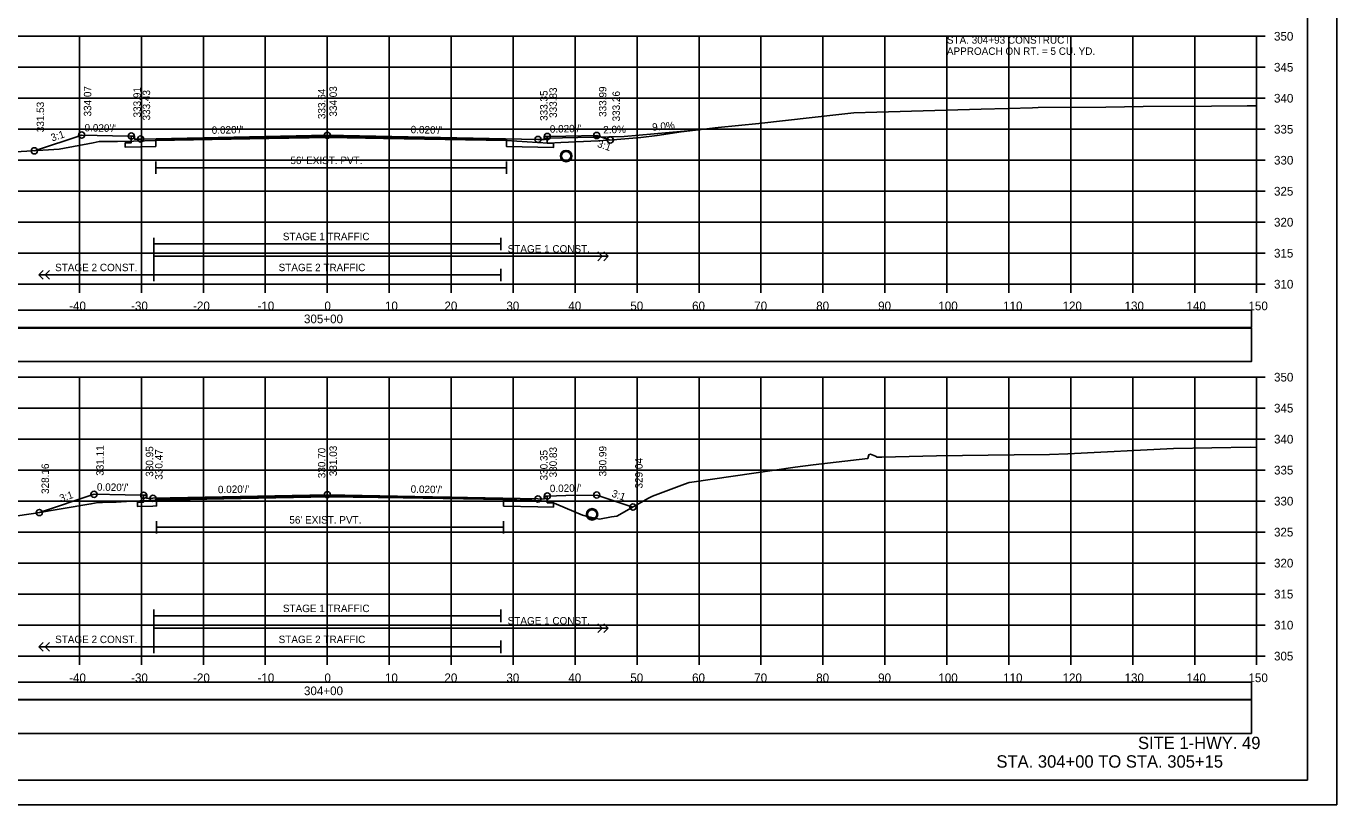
# Model space of a CAD drawing. Extents: x 1368122 to 1710785, y 373130 to 557566.
# Drawn here: x 1369307 to 1369518.5, y 373343.7 to 373469.3 of the extents above; entities that cross this region are included whole.
import ezdxf

# ---------------------------------------------------------------- set-up
doc = ezdxf.new("R2010")
doc.units = 0
for name, color, linetype in [('R_Alt Surface', 7, 'Continuous'), ('R_Axis', 7, 'Continuous'), ('R_Axis Annot', 7, 'Continuous'), ('R_Border', 7, 'Continuous'), ('R_Draft', 7, 'Continuous'), ('R_Drive', 7, 'Continuous'), ('R_Exist Surface', 7, 'Continuous'), ('R_Fin Surface', 7, 'Continuous'), ('R_Grid', 7, 'Continuous'), ('R_No Plot', 7, 'Continuous'), ('R_Striping', 7, 'Continuous'), ('R_Water', 7, 'Continuous'), ('R_Water Annot', 7, 'Continuous'), ('R_Xsect Elev', 7, 'Continuous'), ('R_Xsect Slope', 7, 'Continuous')]:
    doc.layers.add(name, color=color, linetype=linetype)

msp = doc.modelspace()

# ---------------------------------------------------------------- linework, layer by layer
for points in [[(1369206.41, 373420.64), (1369504.71, 373420.64), (1369504.71, 373423.46), (1369206.41, 373423.46)], [(1369206.41, 373415.17), (1369504.71, 373415.17), (1369504.71, 373420.58), (1369206.41, 373420.58)], [(1369206.41, 373360.64), (1369504.71, 373360.64), (1369504.71, 373363.46), (1369206.41, 373363.46)], [(1369206.41, 373355.17), (1369504.71, 373355.17), (1369504.71, 373360.58), (1369206.41, 373360.58)]]:
    msp.add_lwpolyline(points, close=True)
at = {"layer": 'R_Alt Surface'}
for points in [[(1369391.06, 373451.48), (1369391.06, 373450.39), (1369392.06, 373450.37), (1369392.06, 373449.7), (1369389.56, 373449.75), (1369384.51, 373449.85), (1369384.51, 373450.93), (1369355.56, 373451.51), (1369327.87, 373450.95), (1369327.87, 373449.87), (1369325.42, 373449.82), (1369322.92, 373449.77), (1369322.92, 373450.44), (1369323.92, 373450.46), (1369323.92, 373451.55)], [(1369327.87, 373447.43), (1369327.87, 373445.43)], [(1369327.87, 373446.43), (1369384.51, 373446.43)], [(1369384.51, 373447.43), (1369384.51, 373445.43)], [(1369391.06, 373393.48), (1369391.06, 373392.39), (1369392.06, 373392.37), (1369392.06, 373391.7), (1369389.56, 373391.75), (1369384.02, 373391.86), (1369384.02, 373392.94), (1369355.56, 373393.51), (1369328.01, 373392.96), (1369328.01, 373391.88), (1369327.42, 373391.86), (1369324.92, 373391.81), (1369324.92, 373392.48), (1369325.92, 373392.5), (1369325.92, 373393.59)], [(1369328.01, 373389.43), (1369328.01, 373387.43)], [(1369384.02, 373389.43), (1369384.02, 373387.43)], [(1369328.01, 373388.43), (1369384.02, 373388.43)]]:
    msp.add_lwpolyline(points, dxfattribs=at)
at = {"layer": 'R_Axis'}
for p, q in [((1369505.56, 373427.65), (1369505.56, 373467.65)), ((1369506.96, 373467.65), (1369505.56, 373467.65)), ((1369506.96, 373462.65), (1369505.56, 373462.65)), ((1369506.96, 373457.65), (1369505.56, 373457.65)), ((1369506.96, 373452.65), (1369505.56, 373452.65)), ((1369506.96, 373447.65), (1369505.56, 373447.65)), ((1369506.96, 373442.65), (1369505.56, 373442.65)), ((1369506.96, 373437.65), (1369505.56, 373437.65)), ((1369506.96, 373432.65), (1369505.56, 373432.65)), ((1369205.56, 373427.65), (1369505.56, 373427.65)), ((1369315.56, 373426.25), (1369315.56, 373427.65)), ((1369325.56, 373426.25), (1369325.56, 373427.65)), ((1369335.56, 373426.25), (1369335.56, 373427.65)), ((1369345.56, 373426.25), (1369345.56, 373427.65)), ((1369355.56, 373426.25), (1369355.56, 373427.65)), ((1369365.56, 373426.25), (1369365.56, 373427.65)), ((1369375.56, 373426.25), (1369375.56, 373427.65)), ((1369385.56, 373426.25), (1369385.56, 373427.65)), ((1369395.56, 373426.25), (1369395.56, 373427.65)), ((1369405.56, 373426.25), (1369405.56, 373427.65)), ((1369415.56, 373426.25), (1369415.56, 373427.65)), ((1369425.56, 373426.25), (1369425.56, 373427.65)), ((1369435.56, 373426.25), (1369435.56, 373427.65)), ((1369445.56, 373426.25), (1369445.56, 373427.65)), ((1369455.56, 373426.25), (1369455.56, 373427.65)), ((1369465.56, 373426.25), (1369465.56, 373427.65)), ((1369475.56, 373426.25), (1369475.56, 373427.65)), ((1369485.56, 373426.25), (1369485.56, 373427.65)), ((1369495.56, 373426.25), (1369495.56, 373427.65)), ((1369505.56, 373426.25), (1369505.56, 373427.65)), ((1369506.96, 373427.65), (1369505.56, 373427.65)), ((1369505.56, 373367.65), (1369505.56, 373412.65)), ((1369506.96, 373412.65), (1369505.56, 373412.65)), ((1369506.96, 373407.65), (1369505.56, 373407.65)), ((1369506.96, 373402.65), (1369505.56, 373402.65)), ((1369506.96, 373397.65), (1369505.56, 373397.65)), ((1369506.96, 373392.65), (1369505.56, 373392.65)), ((1369506.96, 373387.65), (1369505.56, 373387.65)), ((1369506.96, 373382.65), (1369505.56, 373382.65)), ((1369506.96, 373377.65), (1369505.56, 373377.65)), ((1369506.96, 373372.65), (1369505.56, 373372.65)), ((1369205.56, 373367.65), (1369505.56, 373367.65)), ((1369315.56, 373366.25), (1369315.56, 373367.65)), ((1369325.56, 373366.25), (1369325.56, 373367.65)), ((1369335.56, 373366.25), (1369335.56, 373367.65)), ((1369345.56, 373366.25), (1369345.56, 373367.65)), ((1369355.56, 373366.25), (1369355.56, 373367.65)), ((1369365.56, 373366.25), (1369365.56, 373367.65)), ((1369375.56, 373366.25), (1369375.56, 373367.65)), ((1369385.56, 373366.25), (1369385.56, 373367.65)), ((1369395.56, 373366.25), (1369395.56, 373367.65)), ((1369405.56, 373366.25), (1369405.56, 373367.65)), ((1369415.56, 373366.25), (1369415.56, 373367.65)), ((1369425.56, 373366.25), (1369425.56, 373367.65)), ((1369435.56, 373366.25), (1369435.56, 373367.65)), ((1369445.56, 373366.25), (1369445.56, 373367.65)), ((1369455.56, 373366.25), (1369455.56, 373367.65)), ((1369465.56, 373366.25), (1369465.56, 373367.65)), ((1369475.56, 373366.25), (1369475.56, 373367.65)), ((1369485.56, 373366.25), (1369485.56, 373367.65)), ((1369495.56, 373366.25), (1369495.56, 373367.65)), ((1369505.56, 373366.25), (1369505.56, 373367.65)), ((1369506.96, 373367.65), (1369505.56, 373367.65))]:
    msp.add_line(p, q, dxfattribs=at)
at = {"layer": 'R_Border'}
for q in [(1369513.74, 373553.11), (1369197.56, 373347.65)]:
    msp.add_line((1369513.74, 373347.65), q, dxfattribs=at)
at = {"layer": 'R_Drive'}
for p, q in [((1369415.56, 373452.56), (1369403.5, 373451.48)), ((1369390.56, 373450.98), (1369391.06, 373451.23)), ((1369391.06, 373451.23), (1369403.5, 373451.48))]:
    msp.add_line(p, q, dxfattribs=at)
at = {"layer": 'R_Exist Surface'}
for points in [[(1369300.86, 373448.73), (1369312.27, 373449.41), (1369317.75, 373450.45), (1369318.76, 373450.65), (1369319.32, 373450.65), (1369321.68, 373450.67), (1369324.28, 373450.74), (1369327.87, 373450.86), (1369346.12, 373451.14), (1369355.85, 373451.3), (1369364.63, 373451.16), (1369384.51, 373450.84), (1369389.49, 373450.52), (1369391.27, 373450.43), (1369393.24, 373450.49), (1369399.35, 373450.77), (1369402.28, 373450.99), (1369406.16, 373451.31), (1369408.79, 373451.62), (1369412.7, 373452.22), (1369418.64, 373452.93), (1369425.2, 373453.6), (1369438.15, 373455.05), (1369440.54, 373455.3), (1369444.24, 373455.41), (1369461.07, 373455.91), (1369465.45, 373456.02), (1369469.36, 373456.13), (1369470.32, 373456.17), (1369481.21, 373456.23), (1369487.23, 373456.3), (1369498.29, 373456.36), (1369504.01, 373456.43), (1369505.56, 373456.44)], [(1369294.76, 373388.73), (1369308.13, 373390.65), (1369317.4, 373392.21), (1369318.6, 373392.44), (1369319.26, 373392.45), (1369321.51, 373392.51), (1369323.95, 373392.62), (1369328.01, 373392.81), (1369338.84, 373393.03), (1369355.71, 373393.35), (1369367.81, 373393.17), (1369383.99, 373392.93), (1369384.02, 373392.93), (1369386.14, 373392.88), (1369388.56, 373392.81), (1369391.08, 373392.57), (1369391.69, 373392.53), (1369392.57, 373392.14), (1369396.74, 373390.38), (1369397.57, 373390.19), (1369399.5, 373389.75), (1369401.44, 373390.1), (1369402.31, 373390.23), (1369407.43, 373393.12), (1369408.03, 373393.45), (1369412.81, 373395.22), (1369413.83, 373395.59), (1369413.98, 373395.64), (1369414.39, 373395.71), (1369431.06, 373398.14), (1369433.99, 373398.52), (1369442.79, 373399.54), (1369442.98, 373400.14), (1369443.24, 373400.23), (1369444.04, 373399.89), (1369444.31, 373399.73), (1369445.07, 373399.75), (1369453.89, 373399.96), (1369466.44, 373400.12), (1369472.11, 373400.17), (1369475.09, 373400.27), (1369492.14, 373401.14), (1369504.53, 373401.34), (1369505.56, 373401.32)]]:
    msp.add_lwpolyline(points, dxfattribs=at)
at = {"layer": 'R_Fin Surface'}
for points in [[(1369308.3, 373449.17), (1369315.92, 373451.71), (1369320.92, 373451.61), (1369323.92, 373451.55), (1369324.42, 373451.55), (1369324.42, 373451.05), (1369325.42, 373451.07), (1369355.56, 373451.68), (1369389.56, 373451), (1369390.56, 373450.98), (1369390.56, 373451.48), (1369391.06, 373451.48), (1369394.06, 373451.54), (1369399.06, 373451.64), (1369401.24, 373450.91)], [(1369309.09, 373390.81), (1369317.92, 373393.75), (1369322.92, 373393.65), (1369325.92, 373393.59), (1369326.42, 373393.59), (1369326.42, 373393.09), (1369327.42, 373393.11), (1369355.56, 373393.68), (1369389.56, 373393), (1369390.56, 373392.98), (1369390.56, 373393.48), (1369391.06, 373393.48), (1369394.06, 373393.54), (1369399.06, 373393.64), (1369404.9, 373391.69)]]:
    msp.add_lwpolyline(points, dxfattribs=at)
at = {"layer": 'R_Grid'}
for p, q in [((1369205.56, 373467.65), (1369505.56, 373467.65)), ((1369315.56, 373427.65), (1369315.56, 373467.65)), ((1369325.56, 373427.65), (1369325.56, 373467.65)), ((1369335.56, 373427.65), (1369335.56, 373467.65)), ((1369345.56, 373427.65), (1369345.56, 373467.65)), ((1369355.56, 373427.65), (1369355.56, 373467.65)), ((1369365.56, 373427.65), (1369365.56, 373467.65)), ((1369375.56, 373427.65), (1369375.56, 373467.65)), ((1369385.56, 373427.65), (1369385.56, 373467.65)), ((1369395.56, 373427.65), (1369395.56, 373467.65)), ((1369405.56, 373427.65), (1369405.56, 373467.65)), ((1369415.56, 373427.65), (1369415.56, 373467.65)), ((1369425.56, 373427.65), (1369425.56, 373467.65)), ((1369435.56, 373427.65), (1369435.56, 373467.65)), ((1369445.56, 373427.65), (1369445.56, 373467.65)), ((1369455.56, 373427.65), (1369455.56, 373467.65)), ((1369465.56, 373427.65), (1369465.56, 373467.65)), ((1369475.56, 373427.65), (1369475.56, 373467.65)), ((1369485.56, 373427.65), (1369485.56, 373467.65)), ((1369495.56, 373427.65), (1369495.56, 373467.65)), ((1369505.56, 373427.65), (1369505.56, 373467.65)), ((1369205.56, 373462.65), (1369505.56, 373462.65)), ((1369205.56, 373457.65), (1369505.56, 373457.65)), ((1369205.56, 373452.65), (1369505.56, 373452.65)), ((1369205.56, 373447.65), (1369505.56, 373447.65)), ((1369205.56, 373442.65), (1369505.56, 373442.65)), ((1369205.56, 373437.65), (1369505.56, 373437.65)), ((1369205.56, 373432.65), (1369505.56, 373432.65)), ((1369205.56, 373427.65), (1369505.56, 373427.65)), ((1369205.56, 373412.65), (1369505.56, 373412.65)), ((1369315.56, 373367.65), (1369315.56, 373412.65)), ((1369325.56, 373367.65), (1369325.56, 373412.65)), ((1369335.56, 373367.65), (1369335.56, 373412.65)), ((1369345.56, 373367.65), (1369345.56, 373412.65)), ((1369355.56, 373367.65), (1369355.56, 373412.65)), ((1369365.56, 373367.65), (1369365.56, 373412.65)), ((1369375.56, 373367.65), (1369375.56, 373412.65)), ((1369385.56, 373367.65), (1369385.56, 373412.65)), ((1369395.56, 373367.65), (1369395.56, 373412.65)), ((1369405.56, 373367.65), (1369405.56, 373412.65)), ((1369415.56, 373367.65), (1369415.56, 373412.65)), ((1369425.56, 373367.65), (1369425.56, 373412.65)), ((1369435.56, 373367.65), (1369435.56, 373412.65)), ((1369445.56, 373367.65), (1369445.56, 373412.65)), ((1369455.56, 373367.65), (1369455.56, 373412.65)), ((1369465.56, 373367.65), (1369465.56, 373412.65)), ((1369475.56, 373367.65), (1369475.56, 373412.65)), ((1369485.56, 373367.65), (1369485.56, 373412.65)), ((1369495.56, 373367.65), (1369495.56, 373412.65)), ((1369505.56, 373367.65), (1369505.56, 373412.65)), ((1369205.56, 373407.65), (1369505.56, 373407.65)), ((1369205.56, 373402.65), (1369505.56, 373402.65)), ((1369205.56, 373397.65), (1369505.56, 373397.65)), ((1369205.56, 373392.65), (1369505.56, 373392.65)), ((1369205.56, 373387.65), (1369505.56, 373387.65)), ((1369205.56, 373382.65), (1369505.56, 373382.65)), ((1369205.56, 373377.65), (1369505.56, 373377.65)), ((1369205.56, 373372.65), (1369505.56, 373372.65)), ((1369205.56, 373367.65), (1369505.56, 373367.65))]:
    msp.add_line(p, q, dxfattribs=at)
at = {"layer": 'R_No Plot'}
msp.add_line((1369185.16, 373343.67), (1369518.49, 373343.67), dxfattribs=at)
for points in [[(1369185.15, 373557), (1369518.49, 373557), (1369518.49, 373343.66), (1369185.15, 373343.66)], [(1369431.48, 373553.11), (1369451.1, 373553.11), (1369451.1, 373543.23), (1369467.21, 373543.23), (1369490.41, 373543.23), (1369490.53, 373515.07), (1369513.74, 373515.07), (1369513.74, 373347.65), (1369197.56, 373347.65), (1369197.56, 373553.11)]]:
    msp.add_lwpolyline(points, close=True, dxfattribs=at)
for centre, radius in [((1369315.92, 373451.71), 0.5), ((1369355.56, 373451.68), 0.5), ((1369399.06, 373451.64), 0.5), ((1369323.92, 373451.55), 0.5), ((1369325.42, 373451.07), 0.5), ((1369389.56, 373451), 0.5), ((1369391.06, 373451.48), 0.5), ((1369401.24, 373450.91), 0.5), ((1369308.3, 373449.17), 0.5), ((1369394.11, 373448.33), 0.917), ((1369317.92, 373393.75), 0.5), ((1369325.92, 373393.59), 0.5), ((1369327.42, 373393.11), 0.5), ((1369355.56, 373393.68), 0.5), ((1369389.56, 373393), 0.5), ((1369391.06, 373393.48), 0.5), ((1369399.06, 373393.64), 0.5), ((1369309.09, 373390.81), 0.5), ((1369398.3, 373390.52), 0.917), ((1369404.9, 373391.69), 0.5)]:
    msp.add_circle(centre, radius, dxfattribs=at)
at = {"layer": 'R_Striping'}
for p, q in [((1369399.92, 373432.15), (1369399.21, 373432.85)), ((1369399.21, 373431.44), (1369399.92, 373432.15)), ((1369400.92, 373432.15), (1369400.21, 373432.85)), ((1369400.21, 373431.44), (1369400.92, 373432.15)), ((1369309.01, 373429.15), (1369309.72, 373429.85)), ((1369309.01, 373429.15), (1369327.56, 373429.15)), ((1369309.72, 373428.44), (1369309.01, 373429.15)), ((1369310.01, 373429.15), (1369310.72, 373429.85)), ((1369310.72, 373428.44), (1369310.01, 373429.15)), ((1369399.92, 373372.15), (1369399.21, 373372.85)), ((1369399.21, 373371.44), (1369399.92, 373372.15)), ((1369400.92, 373372.15), (1369400.21, 373372.85)), ((1369400.21, 373371.44), (1369400.92, 373372.15)), ((1369309.01, 373369.15), (1369309.72, 373369.85)), ((1369310.01, 373369.15), (1369310.72, 373369.85)), ((1369309.01, 373369.15), (1369327.56, 373369.15)), ((1369309.72, 373368.44), (1369309.01, 373369.15)), ((1369310.72, 373368.44), (1369310.01, 373369.15))]:
    msp.add_line(p, q, dxfattribs=at)
for points in [[(1369327.56, 373435.15), (1369327.56, 373428.15)], [(1369327.56, 373434.15), (1369383.56, 373434.15)], [(1369383.56, 373435.15), (1369383.56, 373433.15)], [(1369327.56, 373432.15), (1369400.92, 373432.15)], [(1369327.56, 373429.15), (1369383.56, 373429.15)], [(1369383.56, 373430.15), (1369383.56, 373428.15)], [(1369327.56, 373375.15), (1369327.56, 373368.15)], [(1369327.56, 373374.15), (1369383.56, 373374.15)], [(1369383.56, 373375.15), (1369383.56, 373373.15)], [(1369327.56, 373372.15), (1369400.92, 373372.15)], [(1369383.56, 373370.15), (1369383.56, 373368.15)], [(1369327.56, 373369.15), (1369383.56, 373369.15)]]:
    msp.add_lwpolyline(points, dxfattribs=at)
at = {"layer": 'R_Water'}
for centre in [(1369394.11, 373448.33), (1369398.3, 373390.52)]:
    msp.add_circle(centre, 0.75, dxfattribs=at)
at = {"layer": 'R_Xsect Elev'}
for p, q in [((1369355.56, 373451.29), (1369355.56, 373461.29)), ((1369355.56, 373393.35), (1369355.56, 373403.35))]:
    msp.add_line(p, q, dxfattribs=at)

# ---------------------------------------------------------------- texts
at = {"layer": 'R_Axis Annot'}
for s, p in [('350', (1369508.36, 373466.95)), ('345', (1369508.36, 373461.95)), ('340', (1369508.36, 373456.95)), ('335', (1369508.36, 373451.95)), ('330', (1369508.36, 373446.95)), ('325', (1369508.36, 373441.95)), ('320', (1369508.36, 373436.95)), ('315', (1369508.36, 373431.95)), ('310', (1369508.36, 373426.95)), ('-40', (1369313.9, 373423.45)), ('-30', (1369323.9, 373423.45)), ('-20', (1369333.9, 373423.45)), ('-10', (1369344.3, 373423.45)), ('0', (1369355.1, 373423.45)), ('10', (1369364.87, 373423.45)), ('20', (1369374.47, 373423.45)), ('30', (1369384.47, 373423.45)), ('40', (1369394.47, 373423.45)), ('50', (1369404.47, 373423.45)), ('60', (1369414.44, 373423.45)), ('70', (1369424.47, 373423.45)), ('80', (1369434.47, 373423.45)), ('90', (1369444.47, 373423.45)), ('100', (1369454.19, 373423.45)), ('110', (1369464.64, 373423.45)), ('120', (1369474.24, 373423.45)), ('130', (1369484.24, 373423.45)), ('140', (1369494.24, 373423.45)), ('150', (1369504.24, 373423.45)), ('305+00', (1369351.8, 373421.35)), ('350', (1369508.36, 373411.95)), ('345', (1369508.36, 373406.95)), ('340', (1369508.36, 373401.95)), ('335', (1369508.36, 373396.95)), ('330', (1369508.36, 373391.95)), ('325', (1369508.36, 373386.95)), ('320', (1369508.36, 373381.95)), ('315', (1369508.36, 373376.95)), ('310', (1369508.36, 373371.95)), ('305', (1369508.36, 373366.95)), ('-40', (1369313.9, 373363.45)), ('-30', (1369323.9, 373363.45)), ('-20', (1369333.9, 373363.45)), ('-10', (1369344.3, 373363.45)), ('0', (1369355.1, 373363.45)), ('10', (1369364.87, 373363.45)), ('20', (1369374.47, 373363.45)), ('30', (1369384.47, 373363.45)), ('40', (1369394.47, 373363.45)), ('50', (1369404.47, 373363.45)), ('60', (1369414.44, 373363.45)), ('70', (1369424.47, 373363.45)), ('80', (1369434.47, 373363.45)), ('90', (1369444.47, 373363.45)), ('100', (1369454.19, 373363.45)), ('110', (1369464.64, 373363.45)), ('120', (1369474.24, 373363.45)), ('130', (1369484.24, 373363.45)), ('140', (1369494.24, 373363.45)), ('150', (1369504.24, 373363.45)), ('304+00', (1369351.8, 373361.35))]:
    msp.add_text(s, height=1.4, dxfattribs=at).set_placement(p)
at = {"layer": 'R_Draft'}
for s, p in [('SITE 1-HWY. 49', (1369486.41, 373352.65)), ('STA. 304+00 TO STA. 305+15', (1369463.56, 373349.65))]:
    msp.add_text(s, height=2, dxfattribs=at).set_placement(p)
at = {"layer": 'R_Striping'}
for s, p in [('STAGE 1 TRAFFIC', (1369348.39, 373434.75)), ('STAGE 1 CONST.', (1369384.67, 373432.75)), ('STAGE 2 CONST.', (1369311.63, 373429.75)), ('STAGE 2 TRAFFIC', (1369347.71, 373429.75)), ('STAGE 1 TRAFFIC', (1369348.39, 373374.75)), ('STAGE 1 CONST.', (1369384.67, 373372.75)), ('STAGE 2 CONST.', (1369311.63, 373369.75)), ('STAGE 2 TRAFFIC', (1369347.71, 373369.75))]:
    msp.add_text(s, height=1.2, dxfattribs=at).set_placement(p)
at = {"layer": 'R_Water'}
for p in [(1369349.61, 373447.03), (1369349.44, 373389.03)]:
    msp.add_text("56' EXIST. PVT.", height=1.2, dxfattribs=at).set_placement(p)
at = {"layer": 'R_Water Annot'}
for s, p in [('STA. 304+93 CONSTRUCT', (1369455.56, 373466.45)), ('APPROACH ON RT. = 5 CU. YD.', (1369455.56, 373464.65))]:
    msp.add_text(s, height=1.2, dxfattribs=at).set_placement(p)
at = {"layer": 'R_Xsect Elev'}
for s, rotation, p in [('334.07', 90, (1369317.47, 373454.71)), ('333.91', 90, (1369325.47, 373454.55)), ('333.43', 90, (1369326.97, 373454.07)), ('333.64', 90, (1369355.26, 373454.29)), ('334.03', 90, (1369357.11, 373454.68)), ('333.35', 90, (1369391.11, 373454)), ('333.83', 90, (1369392.61, 373454.48)), ('333.99', 90, (1369400.61, 373454.64)), ('333.26', 90, (1369402.79, 373453.91)), ('331.53', 90, (1369309.85, 373452.17)), ('2.0%', 1.1458, (1369400.11, 373451.97)), ('9.0%', 5.1428, (1369408.05, 373452.39)), ('331.11', 90, (1369319.47, 373396.75)), ('330.95', 90, (1369327.47, 373396.59)), ('331.03', 90, (1369357.11, 373396.68)), ('330.99', 90, (1369400.61, 373396.64)), ('330.47', 90, (1369328.97, 373396.11)), ('330.70', 90, (1369355.26, 373396.35)), ('330.35', 90, (1369391.11, 373396)), ('330.83', 90, (1369392.61, 373396.48)), ('329.04', 90, (1369406.45, 373394.69)), ('328.16', 90, (1369310.64, 373393.81))]:
    msp.add_text(s, height=1.2, rotation=rotation, dxfattribs=at).set_placement(p)
at = {"layer": 'R_Xsect Slope'}
for s, rotation, p in [('3:1', 18.4349, (1369311.16, 373450.66)), ("0.020'/'", 358.8542, (1369316.37, 373452.31)), ("0.020'/'", 1.1458, (1369336.92, 373451.9)), ("0.020'/'", 358.8542, (1369369.01, 373452.01)), ("0.020'/'", 1.1458, (1369391.49, 373452.09)), ('3:1', 341.5651, (1369399.03, 373449.82)), ("0.020'/'", 358.8542, (1369318.37, 373394.35)), ("0.020'/'", 1.1458, (1369337.92, 373393.92)), ("0.020'/'", 358.8542, (1369369.01, 373394.01)), ("0.020'/'", 1.1458, (1369391.49, 373394.09)), ('3:1', 18.4349, (1369312.56, 373392.49)), ('3:1', 341.5651, (1369401.35, 373393.4))]:
    msp.add_text(s, height=1.2, rotation=rotation, dxfattribs=at).set_placement(p)

doc.saveas('drawing.dxf')
